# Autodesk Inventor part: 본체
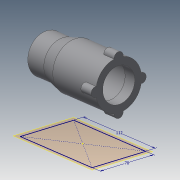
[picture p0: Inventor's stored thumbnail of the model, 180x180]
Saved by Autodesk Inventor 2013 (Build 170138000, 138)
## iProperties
Created: 2019-07
Part Number: 본체
Material: 일반
Document SubType Name: Modeling
Designer: 19
Density: 1 g/cm^3
Author: 19
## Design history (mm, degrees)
sketch "스케치3"
  geometry: L1 (-56, 0)-(56, 0); L2 (-56, 0)-(-56, 25); L3 (-56, 25)-(-31, 25); L4 (-31, 25)-(-11, 30); L5 (-11, 30)-(56, 30); L6 (56, 30)-(56, 0); 2 further points
  constraints: 12 end point, 2 parallel, 2 perpendicular, 1 coincident, 1 horizontal, 1 midpoint
  dimensions: "d7" = 112 distance of L1.start L1.end; "d9" = 60 diameter of L5 L1; "d10" = 45 horizontal distance of L2.end L4.end; "d11" = 25 distance of L2.end L3.end; "d12" = 50 diameter of L3 L1
revolve "회전1" sketch "스케치3" stored, may be unused: angle "d13" = 90 deg
sketch "스케치13"
  geometry: L1 (0, 0)-(0, 30); C1 r 6 at (0, 30)
  constraints: 2 end point, 1 centre point, 1 coincident, 1 vertical, 1 vertical alignment, 1 other
  dimensions: "d52" = 12 diameter of C1
extrude "돌출5" join sketch "스케치13" distance "d53" = 16; taper "d54" = 0 deg
sketch "스케치15"
  geometry: L1 (56, 6)-(56, -6) reference; L2 (56, 0)-(-50, 0); L3 (56, 5.97)-(56, 29.4) reference; L4 (56, 21)-(41, 21); L5 (41, 21)-(41, 24); L6 (41, 24)-(-13, 24); L7 (-13, 24)-(-13, 21); L8 (-13, 21)-(-25, 21); L9 (-25, 21)-(-25, 17.5); L10 (-25, 17.5)-(-43, 17.5); L11 (-43, 17.5)-(-43, 16); L12 (-43, 16)-(-47, 16); L13 (-47, 16)-(-47, 10.5); L14 (-47, 10.5)-(-50, 10.5); L15 (-50, 10.5)-(-50, 0); L16 (56, 21)-(56, 0); 2 further points
  constraints: 28 end point, 10 parallel, 3 perpendicular, 1 collinear, 1 midpoint, 1 point on line
  dimensions: "d62" = 54 distance between parallel lines of L5 L7; "d64" = 48 diameter of L6 L2; "d65" = 15 distance from line of L4.start L5; "d66" = 42 diameter of L4 L2; "d67" = 42 diameter of L8 L2; "d68" = 12 distance of L7.end L8.end; "d69" = 35 diameter of L10 L2; "d70" = 18 distance from line of L9.end L11; "d71" = 4 distance of L11.end L12.end; "d73" = 3 distance from line of L13.end L15; "d74" = 32 diameter of L12 L2; "d75" = 21 diameter of L14 L2
revolve "회전3" sketch "스케치15" stored, may be unused: angle "d76" = 90 deg
node "작업 평면3"
sketch "스케치16"
  geometry: L1 (56, 35)-(-56, 35); L2 (-56, 35)-(-56, -35); L3 (-56, -35)-(56, -35); L4 (56, -35)-(56, 35); L5 (56, 35)-(-56, -35); L6 (-56, 35)-(56, -35); 1 further point
  constraints: 12 end point, 2 midpoint, 2 parallel, 1 horizontal, 1 perpendicular
  dimensions: "d78" = 112 distance of L3.end L2.end; "d79" = 70 distance of L2.end L1.end
node "솔리드2"
pattern_circular "원형 패턴2" dims angle "d56" = 360 deg
